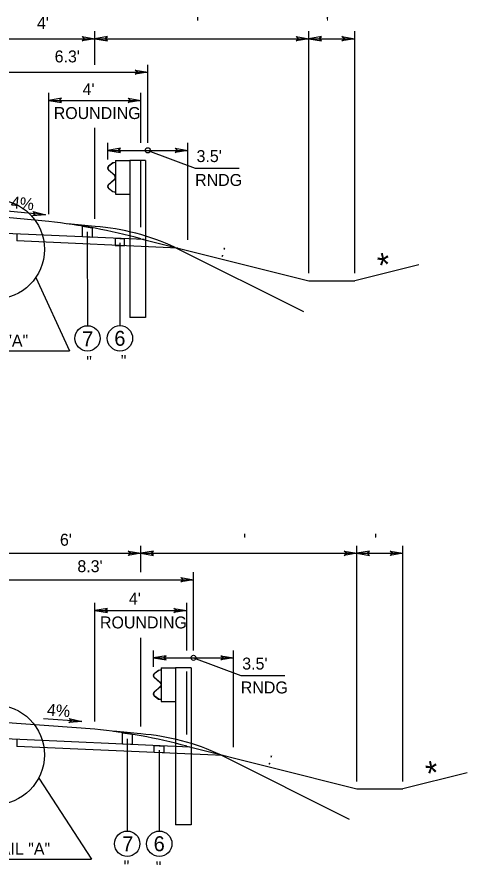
# Model space of a CAD drawing. Extents: x -540 to 1231, y -564 to 421.
# Drawn here: x 32.7 to 85.5, y 185.1 to 284.4 of the extents above; entities that cross this region are included whole.
import ezdxf

# ---------------------------------------------------------------- set-up
doc = ezdxf.new("R2010")
doc.units = 0
doc.layers.add('1', color=7, linetype='Continuous')
doc.layers.add('Des_ Drain_ Ftrs', color=7, linetype='Continuous')

msp = doc.modelspace()

# ---------------------------------------------------------------- linework, layer by layer
at = {"layer": '1'}
for p, q in [((41.846, 278.853), (41.846, 282.776)), ((66.937, 254.411), (66.937, 282.776)), ((72.326, 254.411), (72.326, 282.776)), ((31.069, 281.896), (41.846, 281.896)), ((41.846, 281.896), (66.937, 281.896)), ((66.937, 281.896), (72.326, 281.896)), ((48.063, 269.697), (48.063, 278.853)), ((31.09, 277.973), (48.063, 277.973)), ((36.458, 261.346), (36.458, 275.551)), ((47.234, 269.697), (47.234, 275.551)), ((36.458, 274.671), (47.234, 274.671)), ((41.846, 260.79), (41.846, 271.44)), ((43.371, 267.746), (43.371, 269.697)), ((52.755, 258.34), (52.755, 269.697)), ((43.371, 268.817), (52.755, 268.817)), ((48.063, 268.817), (53.62, 266.746)), ((43.969, 267.349), (43.452, 266.96)), ((43.981, 267.321), (43.47, 266.936)), ((44.284, 267.405), (43.969, 267.349)), ((44.284, 267.375), (43.981, 267.321)), ((44.284, 267.633), (44.284, 263.701)), ((44.284, 267.633), (45.969, 267.633)), ((45.969, 267.633), (45.969, 249.236)), ((47.794, 267.633), (45.969, 267.633)), ((47.234, 259.826), (47.234, 267.615)), ((47.794, 267.633), (47.794, 249.236)), ((43.437, 266.528), (44.169, 265.892)), ((43.456, 266.55), (44.188, 265.915)), ((53.62, 266.746), (58.775, 266.746)), ((44.169, 265.442), (43.437, 264.807)), ((44.188, 265.419), (43.456, 264.784)), ((44.254, 265.705), (44.254, 265.629)), ((44.284, 265.705), (44.284, 265.629)), ((43.452, 264.374), (43.969, 263.985)), ((43.47, 264.398), (43.981, 264.013)), ((43.969, 263.985), (44.284, 263.929)), ((43.981, 264.013), (44.284, 263.959)), ((44.284, 263.701), (45.969, 263.701)), ((36.048, 261.26), (31.571, 261.698)), ((47.65, 258.353), (1.434, 260.37)), ((36.458, 260.466), (31.073, 260.993)), ((43.371, 259.686), (43.371, 259.686)), ((32.716, 259.005), (32.716, 258.196)), ((40.97, 259.252), (40.997, 248.275)), ((47.234, 258.457), (66.937, 253.531)), ((51.574, 257.372), (32.716, 258.196)), ((44.801, 257.969), (44.801, 248.277)), ((51.255, 257.453), (66.307, 249.928)), ((79.861, 255.415), (72.326, 253.531)), ((34.914, 253.903), (38.895, 245.311)), ((66.937, 253.531), (72.326, 253.531)), ((47.794, 249.236), (45.969, 249.236)), ((20.109, 245.311), (38.895, 245.311)), ((31.069, 221.609), (47.234, 221.609)), ((47.234, 219.388), (47.234, 222.489)), ((47.234, 221.609), (72.583, 221.609)), ((72.583, 194.878), (72.583, 222.489)), ((72.583, 221.609), (77.971, 221.609)), ((77.971, 194.878), (77.971, 222.489)), ((53.423, 210.232), (53.423, 219.388)), ((31.061, 218.508), (53.423, 218.508)), ((41.846, 201.877), (41.846, 215.779)), ((52.622, 210.232), (52.622, 215.779)), ((41.846, 214.899), (52.622, 214.899)), ((47.234, 201.322), (47.234, 211.694)), ((48.731, 208.281), (48.731, 210.232)), ((58.115, 198.888), (58.115, 210.232)), ((48.731, 209.352), (58.115, 209.352)), ((53.423, 209.352), (58.98, 207.281)), ((49.329, 207.884), (48.811, 207.495)), ((49.341, 207.856), (48.829, 207.471)), ((49.643, 207.94), (49.329, 207.884)), ((49.643, 207.91), (49.341, 207.856)), ((49.643, 208.168), (49.643, 204.236)), ((49.643, 208.168), (51.328, 208.168)), ((51.328, 208.168), (51.328, 189.771)), ((53.154, 208.168), (51.328, 208.168)), ((52.622, 200.353), (52.622, 207.733)), ((53.154, 208.168), (53.154, 189.771)), ((48.797, 207.063), (49.528, 206.427)), ((48.816, 207.085), (49.547, 206.45)), ((58.98, 207.281), (64.135, 207.281)), ((49.528, 205.977), (48.797, 205.342)), ((49.547, 205.954), (48.816, 205.319)), ((49.614, 206.24), (49.614, 206.164)), ((49.643, 206.24), (49.643, 206.164)), ((48.811, 204.909), (49.329, 204.52)), ((48.829, 204.933), (49.341, 204.548)), ((49.329, 204.52), (49.643, 204.464)), ((49.341, 204.548), (49.643, 204.494)), ((49.643, 204.236), (51.328, 204.236)), ((41.846, 200.997), (31.063, 201.774)), ((40.315, 201.901), (35.828, 202.225)), ((52.978, 198.899), (1.434, 201.15)), ((32.716, 199.784), (32.716, 198.975)), ((45.652, 199.881), (45.652, 189.056)), ((48.731, 200.221), (48.731, 200.221)), ((56.901, 197.918), (32.716, 198.975)), ((52.622, 198.988), (72.583, 193.998)), ((49.415, 198.521), (49.415, 189.056)), ((56.615, 197.988), (71.666, 190.463)), ((85.507, 195.881), (77.971, 193.998)), ((35.273, 195.268), (41.471, 185.779)), ((72.583, 193.998), (77.971, 193.998)), ((53.154, 189.771), (51.328, 189.771)), ((22.685, 185.779), (41.471, 185.779))]:
    msp.add_line(p, q, dxfattribs=at)
for points in [[(41.551, 258.622), (40.405, 258.673), (40.405, 259.941), (41.551, 259.743)], [(45.349, 257.619), (45.349, 258.425), (44.255, 258.476), (44.255, 257.66)], [(45.079, 200.585), (46.225, 200.4), (46.225, 199.194), (45.079, 199.244)], [(48.81, 199.072), (49.957, 199.022), (49.957, 198.212), (48.81, 198.262)]]:
    msp.add_lwpolyline(points, close=True, dxfattribs=at)
for centre, radius in [((48.063, 268.817), 0.3), ((30.104, 257.216), 5.838), ((40.997, 246.789), 1.485), ((44.801, 246.791), 1.485), ((53.423, 209.352), 0.3), ((30.104, 197.995), 5.838), ((45.652, 187.57), 1.485), ((49.415, 187.57), 1.485)]:
    msp.add_circle(centre, radius, dxfattribs=at)
for centre, radius, start, end in [((43.619, 266.738), 0.278, 126.97989, 229.02099), ((43.619, 266.738), 0.249, 126.97989, 229.02099), ((44.006, 265.705), 0.249, 0, 49.03649), ((44.006, 265.629), 0.249, 310.96352, 0), ((44.006, 265.705), 0.278, 0, 49.03649), ((44.006, 265.629), 0.278, 310.96352, 0), ((43.619, 264.596), 0.278, 130.97902, 233.02011), ((43.619, 264.596), 0.249, 130.97902, 233.02011), ((29.572, 193.632), 67.188, 74.75934, 84.1179), ((31.048, 159.243), 101.244, 83.86333, 85.67746), ((39.748, 232.621), 27.368, 65.13739, 85.55132), ((48.979, 207.273), 0.278, 126.97989, 229.02099), ((48.979, 207.273), 0.249, 126.97989, 229.02099), ((49.365, 206.24), 0.249, 0, 49.03649), ((49.365, 206.164), 0.249, 310.96352, 0), ((49.365, 206.24), 0.278, 0, 49.03649), ((49.365, 206.164), 0.278, 310.96352, 0), ((48.979, 205.132), 0.278, 130.97902, 233.02011), ((48.979, 205.132), 0.249, 130.97902, 233.02011), ((34.962, 134.163), 67.188, 74.76105, 84.11962), ((36.408, 99.779), 101.244, 83.86333, 85.67746), ((45.108, 173.156), 27.368, 65.13739, 85.55132)]:
    msp.add_arc(centre, radius, start, end, dxfattribs=at)
at = {"layer": 'Des_ Drain_ Ftrs'}
for points in [[(41.846, 281.896), (40.357, 281.648), (40.652, 281.896), (40.357, 282.144)], [(41.846, 281.896), (43.334, 281.648), (43.039, 281.896), (43.334, 282.144)], [(66.937, 281.896), (65.449, 281.648), (65.744, 281.896), (65.449, 282.144)], [(66.937, 281.896), (68.426, 281.648), (68.131, 281.896), (68.426, 282.144)], [(72.326, 281.896), (70.837, 281.648), (71.132, 281.896), (70.837, 282.144)], [(48.063, 277.973), (46.575, 277.725), (46.87, 277.973), (46.575, 278.221)], [(36.458, 274.671), (37.946, 274.423), (37.651, 274.671), (37.946, 274.92)], [(47.234, 274.671), (45.746, 274.423), (46.041, 274.671), (45.746, 274.92)], [(43.371, 268.817), (44.86, 268.569), (44.565, 268.817), (44.86, 269.065)], [(52.755, 268.817), (51.267, 268.569), (51.562, 268.817), (51.267, 269.065)], [(36.048, 261.26), (34.543, 261.156), (34.861, 261.375), (34.591, 261.651)], [(47.234, 221.609), (45.746, 221.36), (46.041, 221.609), (45.746, 221.857)], [(47.234, 221.609), (48.723, 221.36), (48.428, 221.609), (48.723, 221.857)], [(72.583, 221.609), (71.095, 221.36), (71.39, 221.609), (71.095, 221.857)], [(72.583, 221.609), (74.071, 221.36), (73.776, 221.609), (74.071, 221.857)], [(77.971, 221.609), (76.483, 221.36), (76.778, 221.609), (76.483, 221.857)], [(53.423, 218.508), (51.934, 218.26), (52.229, 218.508), (51.934, 218.757)], [(41.846, 214.899), (43.334, 214.651), (43.039, 214.899), (43.334, 215.147)], [(52.622, 214.899), (51.134, 214.651), (51.429, 214.899), (51.134, 215.147)], [(48.731, 209.352), (50.219, 209.104), (49.924, 209.352), (50.219, 209.601)], [(58.115, 209.352), (56.626, 209.104), (56.921, 209.352), (56.626, 209.601)], [(40.315, 201.901), (38.813, 201.759), (39.125, 201.986), (38.848, 202.255)]]:
    msp.add_lwpolyline(points, close=True, dxfattribs=at)

# ---------------------------------------------------------------- texts
at = {"layer": '1'}
for s, height, p in [("4'", 1.4, (35.067, 283.047)), ("  '", 1.4, (52.696, 283.047)), (" '", 1.4, (68.436, 283.047)), ("6.3'", 1.4, (37.139, 279.124)), ("4'", 1.4, (40.417, 275.287)), ('ROUNDING', 1.4, (37.029, 272.487)), ("3.5'", 1.4, (53.779, 267.445)), ('RNDG', 1.4, (53.61, 264.645)), ('7', 1.75, (40.359, 245.845)), ('6', 1.75, (44.137, 245.916)), ('SEE DETAIL "A"', 1.4, (20.119, 245.814)), (' "', 1.4, (40.323, 243.333)), (' "', 1.4, (44.376, 243.432)), ("6'", 1.4, (37.761, 222.49)), ("  '", 1.4, (58.212, 222.49)), (" '", 1.4, (74.082, 222.49)), ("8.3'", 1.4, (39.805, 219.389)), ("4'", 1.4, (45.844, 215.599)), ('ROUNDING', 1.4, (42.455, 212.799)), ("3.5'", 1.4, (59.139, 207.981)), ('RNDG', 1.4, (58.97, 205.181)), ('7', 1.75, (45.062, 186.695)), ('6', 1.75, (48.751, 186.696)), ('SEE DETAIL "A"', 1.4, (22.694, 186.283)), (' "', 1.4, (44.709, 184.211)), (' "', 1.4, (48.472, 184.115))]:
    msp.add_text(s, height=height, dxfattribs=at).set_placement(p)
for s, height, rotation, p in [('4%', 1.4, 354.12681, (31.949, 262.058)), (' : ', 1.4, 345.77179, (56.036, 256.546)), ('*', 2.8, 12.84793, (75.416, 253.885)), ('4%', 1.4, 355.59358, (36.197, 202.595)), (' : ', 1.4, 345.77179, (61.553, 197.045)), ('*', 2.8, 12.84793, (81.062, 194.351))]:
    msp.add_text(s, height=height, rotation=rotation, dxfattribs=at).set_placement(p)

doc.saveas('drawing.dxf')
